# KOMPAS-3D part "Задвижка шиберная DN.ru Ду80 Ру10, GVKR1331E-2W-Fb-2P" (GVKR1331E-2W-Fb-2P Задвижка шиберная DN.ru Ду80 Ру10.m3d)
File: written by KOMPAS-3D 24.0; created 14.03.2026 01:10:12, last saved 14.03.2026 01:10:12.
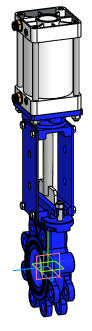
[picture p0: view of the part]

Document properties: Автор: DN.RU; Полное имя файла: D:\PROJECT CAD\DN.RU\...192.(ACTUALE) GVKR1331E-2W-Fb-2P Задвижка шиберная DN.ru Ру6-10\DN80\GVKR1331E-2W-Fb-2P Задвижка шиберная DN.ru Ду80 Ру10.m3d

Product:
- Body: Твердое тело1  | qty 1
    Масса: 26.596756
- Part/product: Задвижка шиберная DN.ru Ду80 Ру10  | designation GVKR1331E-2W-Fb-2P
    Масса: 14
    Раздел спецификации: Прочие изделия
    Комментарий: D040-07408
    Примечание: D040-07408
    additional columns: Чугун, серый

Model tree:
1. Твердое тело1  (labels: Твердое тело1)

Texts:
  GVKR1331E-2W-Fb-2P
